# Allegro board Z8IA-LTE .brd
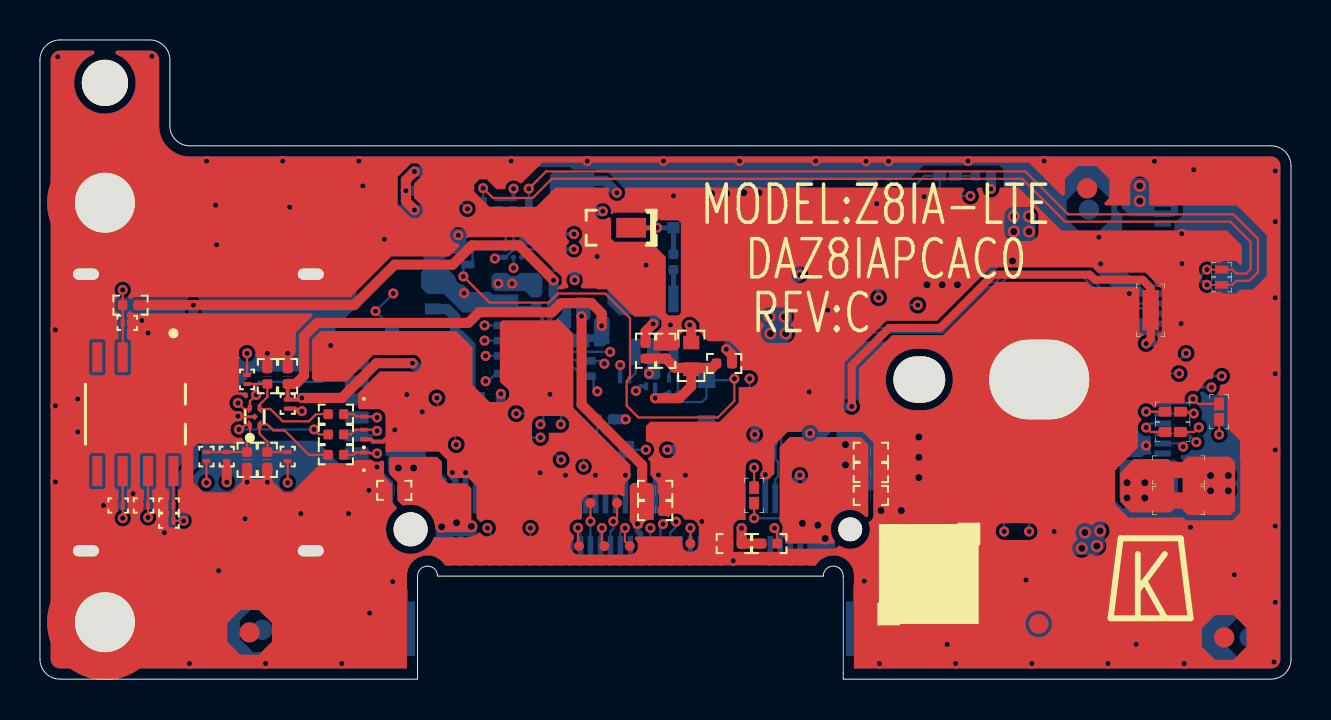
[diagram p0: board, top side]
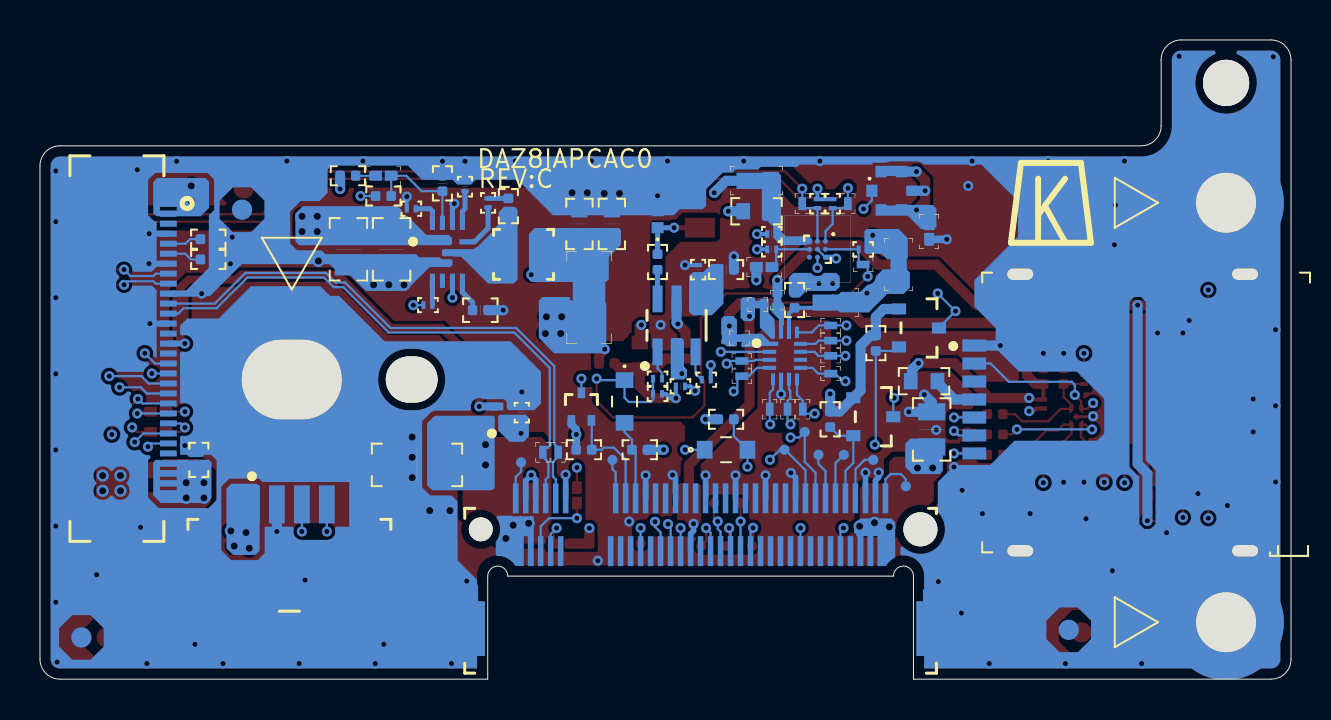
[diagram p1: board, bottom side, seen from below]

Outline 62.6 x 32 mm; copper layers: TOP, SGND, IN1, SVCC, IN2, IN3, SGND1, IN4, SGND2, BOTTOM. Coordinates in mm from the lower left corner of the outline.
Outline path: 0,31 0,1 arc(0.29,0.29) 1,0 18.89,0 18.89,5.16 arc(19.39,5.66) 19.89,5.16 39.19,5.16 arc(39.69,5.66) 40.19,5.16 40.19,0 61.6,0 arc(62.31,0.29) 62.6,1 62.6,25.7 arc(62.31,26.41) 61.6,26.7 7.5,26.7 arc(6.79,26.99) 6.5,27.7 6.5,31 arc(6.21,31.71) 5.5,32 1,32 arc(0.29,31.71) 0,31

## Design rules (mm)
constraint set DEFAULT: min track width 0.114
net group DFP-S4.5(3.5: nets USB2_3_A1_S_N USB2_3_A1_S_N_R USB2_3_A1_S_P USB2_3_A1_S_P_R
net group W4.5(3.5: nets 2ND_MBCLK 2ND_MBDATA I2C_DX_LTE_1V8_RSUB_SCL I2C_DX_LTE_1V8_RSUB_SDA

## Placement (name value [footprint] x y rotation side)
C1  *0.1u/50V_4  [C0402]  54.65 10.98 270 bottom
C2  USIM@0.1u/50V_4  [C0402]  12.39 15.17 270 top
C3  USIM@33p/50V_4  [C0402]  10.36 10.98 270 top
C4  USIM@33p/50V_4  [C0402]  11.38 10.98 270 top
C5  USIM@33p/50V_4  [C0402]  11.38 15.17 90 top
C6  1u/6.3V_4  [C0402]  34.72 6.79 0 top
C7  0.1u/50V_4  [C0402]  41.58 11.36 180 top
C8  100u/6.3V_12  [C1206]  43.73 10.72 180 bottom
C9  33p/50V_4  [C0402]  41.58 10.34 180 top
C10  10P/50V_4  [C0402]  41.58 9.2 180 top
C11  1u/10V_2  [C0201]  38.49 13.34 90 bottom
C14  0.1u/50V_4  [C0402]  30.78 9.45 180 top
C15  33p/50V_4  [C0402]  30.78 8.44 0 top
C16  22U/6.3V_8  [C0805]  17.98 12.5 270 bottom
C17  330p/25V_4  [C0402]  17.73 9.45 0 top
C18  ESIM@1u/6.3V_2  [C0201]  6.45 7.93 0 top
C19  ESIM@0.1u/16V_2  [C0201]  6.45 8.69 0 top
C21  ESIM@33p/25V_2  [C0201]  5.18 8.69 0 top
C22  ESIM@33p/25V_2  [C0201]  3.91 8.69 0 top
C23  ESIM@33p/25V_2  [C0201]  4.36 17.84 180 top
C24  22u/25V_8  [C0805]  45 21.52 90 bottom
C25  0.22u/25V_4  [C0402]  39.16 23.68 90 bottom
C26  *22u/25V_8  [C0805]  47.16 21.52 90 bottom
C27  1u/10V_2  [C0201]  41.33 24.66 90 bottom
C28  *P4@1u/6.3V_2  [C0201]  30.55 14.66 180 bottom
C29  *P4@100p/50V_4  [C0402]  31.32 16.44 270 top
C30  10u/16V_6  [C0603]  33.98 22.79 270 bottom
C31  10u/16V_6  [C0603]  35.61 22.79 270 bottom
C32  *1u/16V_4  [C0402]  42.46 24.82 270 bottom
C33  4.7u/10V_4  [C0402_2]  40.56 18.47 0 bottom
C34  *P4@1u/6.3V_2  [C0201]  29.67 20.5 90 bottom
C35  *P4@100p/50V_4  [C0402]  28.27 20.5 0 bottom
C45636  SPIN@0.1u/25V_2  [C0201]  25.98 22.28 0 bottom
C45637  SPIN@0.1u/25V_2  [C0201]  25.98 21.52 0 bottom
CN1  50278-00401-V01  [WTB-50278-00401-V01-4P-L]  50.12 3.83 180 bottom
CN3  APCI0157-P001A  [NGFF-APCI0157-P001A-75P-KB]  29.54 7.5 180 bottom
CN4  51540-03001-V01  [51540-03001-V01-30P-L]  59.35 16.55 270 bottom
CN5  USIM@155-1001302601  [SIMCARD-155-1001302601-7P-R]  7.25 13.35 90 bottom
D1  USIM@MESD11LH5.0CT5G  [R0201]  12.39 13.77 270 top
D2  USIM@TPD4E101DPWR  [SON4-0_8X0_8-48-5P-0_4H]  10.74 13.14 270 top
D3  *P4@AZ5325-01F.R7GR  [D-1X0_6-0_6H]  31.7 23.03 90 bottom
D26  RB500V-40  [D-1_85X1_25-2P-0_95H]  33.35 13.9 270 bottom
D13142  USIM@PESD5V0F1BSF  [D-0_6X0_3-0_32H-SMT]  16.2 11.11 90 top
D13143  USIM@PESD5V0F1BSF  [D-0_6X0_3-0_32H-SMT]  16.2 12.25 90 top
D13144  USIM@PESD5V0F1BSF  [D-0_6X0_3-0_32H-SMT]  16.2 13.39 270 top
D13145  RB500V-40  [D-1_85X1_25-2P-0_95H]  28.27 11.49 180 bottom
F1  USIM@SMD0603P100SLR/1A/6V_0603  [R0603]  18.36 14.92 0 bottom
HOLE1  *h-c228d118p2  [H-C228D118P2]  3.25 23.85 0 top
HOLE2  *h-c228d118p2  [H-C228D118P2]  3.25 2.85 0 top
HOLE3  *h-c315d197x157p2  [H-C315D197X157P2]  50 15 0 top
HOLE4  *h-o102x91d102x91n  [H-O102X91D102X91N]  44 15 0 top
HOLE5  *h-c91d91n  [H-C91D91N]  3.25 29.85 0 top
J11  SPIN@20449-001E  [ANTENNA-20449-001E-4P]  20 24.45 270 bottom
L1  2.2uH_3.2x2.5x1.5  [L3X2_5-1_5]  38.4 21.27 180 bottom
L2  USIM@BLM15PX330SN1D  [R0402]  14.81 13.26 180 top
L3  USIM@BLM15PX330SN1D  [R0402]  14.81 12.25 180 top
L4  USIM@BLM15PX330SN1D  [R0402]  14.81 11.23 180 top
NOREF  -  [unnamed]  44.47 5.26 0 top
NOREF#2  -  [#2]  23.8 -31.19 0 top
NOREF#3  -  [#2]  55.59 5.05 0 top
NOREF#4  -  [#2]  -27 -71.32 0 top
NOREF#5  -  [unnamed#3]  52.4 24.57 0 top
NOREF#6  -  [unnamed#3]  10.49 2.34 180 top
NOREF#7  -  [unnamed#3]  59.26 2.09 0 top
NOREF#8  -  [#2]  12 23.85 180 bottom
NOREF#9  -  [unnamed#3]  60.53 2.09 180 bottom
NOREF#10  -  [unnamed#3]  11.12 2.47 0 bottom
NOREF#11  -  [unnamed#3]  52.49 23.5 180 bottom
Q1  PMZ370UNE  [ESD3-0_985X0_585]  39.76 13.3 270 bottom
Q2  2N7002KTB  [SOT23-1_38-5-3P]  35.51 13.65 270 bottom
Q3  PJA138K  [SOT23-2-95-3P]  20.9 13.14 0 bottom
Q4  PJA138K  [SOT23-2-95-3P]  18.62 17.58 0 bottom
R1  *Short_4  [S0402]  56.68 12.38 0 top
R3  *Short_4  [S0402]  56.68 13.39 180 top
R4  USIM@15K_5%_2  [R0201]  9.35 11.14 90 top
R5  USIM@22_5%_2  [R0201]  10.36 15 270 top
R6  USIM@22_5%_2  [R0201]  12.39 11.14 90 top
R7  USIM@22_5%_2  [R0201]  8.33 11.14 90 top
R8  *Short_4  [S0402]  35.73 9.2 90 top
R9  10K_5%_4  [R0402]  36.5 6.79 180 top
R10  *EM06@Short_2  [S0201]  37.44 11.36 90 bottom
R11  *EM06@Short_2  [S0201]  36.67 11.36 90 bottom
R12  10K_5%_4  [R0402]  35.38 11.49 0 bottom
R13  10K_5%_4  [R0402]  32.59 11.49 0 bottom
R17  *EM06@Short_2  [S0201]  26.69 18.75 180 bottom
R32  10K_5%_4  [R0402]  23.06 13.01 90 bottom
R33  *P4@470_1%_4  [R0402]  31.7 20.88 90 bottom
R34  3.3_1%_2  [R0201]  40.18 23.84 90 bottom
R35  *Short_12  [S1206]  35.13 19.11 90 bottom
R36  *P4@43_5%_4  [R0402]  30.3 16.44 270 top
R37  *P4@4.7K_1%_2  [R0201]  31.7 14.28 0 bottom
R38  *P4@0_5%_2  [R0201]  29.26 14.99 180 bottom
R39  10K_1%_2  [R0201]  44.02 23.55 0 bottom
R40  100K_1%_2  [R0201]  43.19 18.73 0 bottom
R41  *Short_4  [S0402]  59 13.39 270 top
R42  10K_5%_4  [R0402]  20.78 16.82 90 bottom
R59  *EM06@Short_2  [S0201]  23.03 15.3 180 bottom
R60  *EM06@Short_2  [S0201]  26.08 13.52 270 bottom
R61  *EM06@Short_2  [S0201]  23.03 17.71 180 bottom
R62  *EM06@Short_2  [S0201]  27.61 17.07 0 bottom
R63  *EM06@Short_2  [S0201]  25.7 18.98 90 bottom
R64  *EM06@Short_2  [S0201]  27.48 15.93 0 bottom
R65  *EM06@Short_2  [S0201]  25.19 13.52 270 bottom
R66  *EM06@Short_2  [S0201]  23.03 16.19 180 bottom
R75  *EM06@Short_2  [S0201]  27.48 15.17 180 bottom
R76  *EM06@Short_2  [S0201]  24.43 13.52 90 bottom
R77  *EM06@Short_2  [S0201]  23.03 16.95 0 bottom
R299  SPIN@2.2K_1%_2  [R0201]  22.93 23.81 90 bottom
R316  SPIN@2.2K_1%_2  [R0201]  23.7 23.81 90 bottom
R343  *P4@0.01_1%_6  [R0603]  32.59 16.19 90 top
R344  **P4@0_5%_4  [R0402]  34.24 15.8 0 top
R345  *Short_0603  [S0603]  22.93 18.85 180 bottom
R346  *0_5%_4  [R0402]  24.84 18.98 90 bottom
R347  ESIM@10K_5%_4  [R0402]  4.53 18.73 180 top
R348  10K_5%_4  [R0402]  47.19 25.2 180 bottom
R349  *Short_4  [S0402]  45.41 25.2 180 bottom
R350  *0_5%_4  [R0402]  45.41 24.19 0 bottom
R558_46  SPIN@2.2K_1%_2  [R0201]  21.41 21.52 180 bottom
R4700  *SPIN@Short_0201  [S0201]  24.46 23.81 90 bottom
R4701  *SPIN@Short_0201  [S0201]  22.17 23.81 90 bottom
R4702  *SPIN@Short_0201  [S0201]  21.41 20.76 180 bottom
R4704  *SPIN@Short_0402  [S0402]  26.36 20.63 180 bottom
R4705  *SPIN@Short_0402  [S0402]  18.11 22.41 270 bottom
R69070  ESIM@0_5%_4  [R0402]  54.18 22.03 180 bottom
R69071  USIM@0_5%_4  [R0402]  54.18 21.01 180 bottom
R69072  *Short_0603  [S0603]  56.97 10.47 180 top
R69073  *Short_0603  [S0603]  56.97 8.95 180 top
R69074  *Short_0603  [S0603]  55.57 18.47 270 top
R69075  *P4@0_5%_2  [R0201]  31.7 15.04 0 bottom
R69076  *SPIN@Short_0603  [S0603]  26.74 24.95 180 bottom
R69077  *SPIN@Short_0603  [S0603]  19.63 20.76 270 bottom
R69078  *SPIN@0.01_1%_6  [R0603]  26.74 23.42 180 bottom
R69079  10K_5%_4  [R0402]  28.27 13.01 0 bottom
R69080  *Short_0201  [S0201]  59.13 19.74 0 top
R69081  *Short_0201  [S0201]  59.13 20.5 0 top
SPR1  *P4@FDZDJ00101  [EMIPAD59X39]  28.43 22.6 180 top
TP1  *TP  [TP2050]  32.54 6.79 0 top
TP2  *TP  [TP2050]  33.96 10.98 180 bottom
TP3  *TP  [TP2050]  20.9 10.98 180 bottom
TP4  *TP  [TP2050]  19.27 9.66 180 bottom
TP5  *TP  [TP2050]  38.53 10.85 180 bottom
TP6  *TP  [TP2050]  25.35 11.49 180 bottom
TP7  *TP  [TP2050]  24.33 12.38 180 bottom
TP8  *TP  [TP2050]  23.65 11.23 180 bottom
TP9  *TP  [TP2050]  22.38 11.23 180 bottom
TP10  *TP  [TP2050]  29.51 6.66 0 top
TP11  *TP  [TP2050]  26.97 6.66 0 top
TP12  *TP  [TP2050]  28.24 6.66 0 top
TP13  *TP  [TP2050]  28.88 8.82 0 top
TP14  *TP  [TP2050]  27.54 8.82 0 top
U1  NX3DV2567GU  [QFN16-2_6X1_8-4-0_55H]  25.32 16.19 270 bottom
U4  NB680GD-Z  [QFN12-2X3-5]  42.21 21.39 270 bottom
U5  *P4@IQS231A01311000TSR  [TSOT23-6-2_8-95-6P-1_1H]  30.75 17.71 270 bottom
U6  ESIM@MFF2-EUICC-MFONLY  [DFN8-6X5-1_27-9P-0_95H]  4.77 13.26 180 top
U9314  SPIN@SX9310ICSTRT  [BGA9-SEMTECH-SX9310]  23.7 21.52 0 bottom

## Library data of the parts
C1 C2 C6-C11 C14 C19 C21 C24-C35 C45636 C45637 = CAP_NON-POL_BGM
C3-C5 C15 = CAP_NP
C16 = C_7
C17 C18 C22 C23 = CAP NON-POL_BGM
CN1 = 50278-00401-V01_4P_BGM
CN3 = NGFF_79P_BKEY_BGM
CN4 = FFCFPC_30P_BGM
CN5 = SIMCARD_7P_4F_BGM
D1 = ZENER-2_0
D2 = TPD4E101DPWR_2
D3 D13142-D13144 = TVS_DIODE_BGM
D26 D13145 = Schottky_DIODE_BGM
F1 = FUSE_BGM
HOLE1-HOLE5 = 3x2_6.1
J11 = RF_4P_V2_BGM
L1 = INDUCTOR_BGM
L2-L4 = BEAD_BGM
Q1 = MOS-N_3P_ESD_123_1_BGM
Q2-Q4 = MOS-N_3P_ESD_BGM
R1 R3-R13 R17 R32-R42 R59-R66 R75-R77 R299 R316 R344 R346-R350 R558_46 R69070 R69071 R69075 R69079 = RES_BGM
R343 R69078 = R_Current_SEN_BGM
R345 R4700-R4702 R4704 R4705 R69072-R69074 R69076 R69077 R69080 R69081 = SHORTPAD_V01_BGM
SPR1 = SPRING_BGM
TP1-TP14 = TP_BGM
U1 = NX3DV2567GU_16P_BGM
U4 = NB680
U5 = IQS231A_6P_BGM
U6 = MFF2-EUICC-MFONLY_8P_BGM
U9314 = SX9310ICSTRT_9P_BGM

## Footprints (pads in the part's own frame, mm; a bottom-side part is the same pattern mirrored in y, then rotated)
51540-03001-V01-30P-L
  rect 0.305x0.838 smd: 1(-7.25,3.175) 2(-6.75,3.175) 3(-6.25,3.175) 4(-5.75,3.175) 5(-5.25,3.175) 6(-4.75,3.175) 7(-4.25,3.175) 8(-3.75,3.175) 9(-3.25,3.175) 10(-2.75,3.175) 11(-2.25,3.175) 12(-1.75,3.175) 13(-1.25,3.175) 14(-0.75,3.175) 15(-0.25,3.175) 16(0.25,3.175) 17(0.75,3.175) 18(1.25,3.175) 19(1.75,3.175) 20(2.25,3.175) 21(2.75,3.175) 22(3.25,3.175) 23(3.75,3.175) 24(4.25,3.175) 25(4.75,3.175) 26(5.25,3.175) 27(5.75,3.175) 28(6.25,3.175) 29(6.75,3.175) 30(7.25,3.175)
  rect 0.787x2.007 smd: 31(-8.95,0) 32(8.95,0)
ANTENNA-20449-001E-4P
  rect 0.61x0.559 smd: 1(0,-0.975)
  custom 0.145x0.145 smd: 2(0.96,0) 3(-0.96,0)
  rect 0.508x0.508 smd: 4(0,1)
BGA9-SEMTECH-SX9310
  round 0.254 smd: A1(-0.4,-0.4) A2(-0.4,0) A3(-0.4,0.4) B1(0,-0.4) B2(0,0) B3(0,0.4) C1(0.4,-0.4) C2(0.4,0) C3(0.4,0.4)
C0201
  rect 0.203x0.381 smd: 1(-0.225,0) 2(0.225,0)
C0402
  custom 0.12x0.12 smd: 1(0.39,0) 2(-0.39,0)
C0402_2
  custom 0.12x0.12 smd: 1(0.39,0) 2(-0.39,0)
C0603
  rect 0.686x0.813 smd: 1(0.6,0) 2(-0.6,0)
C0805
  rect 0.864x1.372 smd: 1(0.88,0) 2(-0.88,0)
C1206
  rect 1.219x1.626 smd: 1(1.4,0) 2(-1.4,0)
D-0_6X0_3-0_32H-SMT
  custom 0.051x0.051 smd: 1(-0.242,0) 2(0.242,0)
D-1_85X1_25-2P-0_95H
  rect 0.787x0.889 smd: 1(-1.07,0) 2(1.07,0)
D-1X0_6-0_6H
  rect 0.559x0.61 smd: 1(-0.425,0) 2(0.425,0)
DFN8-6X5-1_27-9P-0_95H
  rect 0.508x1.499 smd: 1(-1.905,-2.85) 2(-0.635,-2.85) 3(0.635,-2.85) 4(1.905,-2.85) 5(1.905,2.85) 6(0.635,2.85) 7(-0.635,2.85) 8(-1.905,2.85)
  rect 4.191x3.404 smd: 9(0,0)
EMIPAD59X39
  rect 1.499x0.991 smd: 1(-1.15,0)
ESD3-0_985X0_585
  custom 0.062x0.062 smd: 1(0.35,-0.225) 2(0.35,0.225)
  custom 0.1x0.1 smd: 3(-0.35,0)
H-C91D91N
  round 2.311 hole 2.311 unplated: (0,0)
H-C228D118P2
  round 5.791 hole 2.997: 1(0,0)
H-C315D197X157P2
  round 8.001 hole 5.004x3.988: 1(0,0)
H-O102X91D102X91N
  oval 2.591x2.311 hole 2.591x2.311 unplated: (0,0)
L3X2_5-1_5
  rect 1.245x1.194 smd: 1(-1.125,0) 2(1.125,0)
NGFF-APCI0157-P001A-75P-KB
  round 1.194 hole 1.194 unplated: (-11,0)
  round 1.702 hole 1.702 unplated: (11,0)
  rect 0.279x1.499 smd: 1(-9.25,1.55) 2(-9,-1.09) 3(-8.75,1.55) 4(-8.5,-1.09) 5(-8.25,1.55) 6(-8,-1.09) 7(-7.75,1.55) 8(-7.5,-1.09) 9(-7.25,1.55) 10(-7,-1.09) 11(-6.75,1.55) 20(-4.5,-1.09) 21(-4.25,1.55) 22(-4,-1.09) 23(-3.75,1.55) 24(-3.5,-1.09) 25(-3.25,1.55) 26(-3,-1.09) 27(-2.75,1.55) 28(-2.5,-1.09) 29(-2.25,1.55) 30(-2,-1.09) 31(-1.75,1.55) 32(-1.5,-1.09) 33(-1.25,1.55) 34(-1,-1.09) 35(-0.75,1.55) 36(-0.5,-1.09) 37(-0.25,1.55) 38(0,-1.09) 39(0.25,1.55) 40(0.5,-1.09) 41(0.75,1.55) 42(1,-1.09) 43(1.25,1.55) 44(1.5,-1.09) 45(1.75,1.55) 46(2,-1.09) 47(2.25,1.55) 48(2.5,-1.09) 49(2.75,1.55) 50(3,-1.09) 51(3.25,1.55) 52(3.5,-1.09) 53(3.75,1.55) 54(4,-1.09) 55(4.25,1.55) 56(4.5,-1.09) 57(4.75,1.55) 58(5,-1.09) 59(5.25,1.55) 60(5.5,-1.09) 61(5.75,1.55) 62(6,-1.09) 63(6.25,1.55) 64(6.5,-1.09) 65(6.75,1.55) 66(7,-1.09) 67(7.25,1.55) 68(7.5,-1.09) 69(7.75,1.55) 70(8,-1.09) 71(8.25,1.55) 72(8.5,-1.09) 73(8.75,1.55) 74(9,-1.09) 75(9.25,1.55)
  rect 1.194x2.743 smd: 76(-11.385,-4.97) 77(11.385,-4.97)
QFN12-2X3-5
  rect 0.254x1.499 smd: 1(-0.5,-0.55) 2(0.5,-0.55) 7(0,0.55)
  rect 0.711x0.254 smd: 3(1.45,-0.75) 4(1.45,-0.25) 5(1.45,0.25) 6(1.45,0.75) 9(-1.45,0.75) 10(-1.45,0.25) 11(-1.45,-0.25) 12(-1.45,-0.75)
  rect 0.254x0.711 smd: 8(-0.5,0.95)
QFN16-2_6X1_8-4-0_55H
  rect 0.203x0.762 smd: 1(-0.6,-0.725)
  rect 0.203x0.66 smd: 2(-0.2,-0.775) 3(0.2,-0.775) 4(0.6,-0.775) 9(0.6,0.775) 10(0.2,0.775) 11(-0.2,0.775) 12(-0.6,0.775)
  rect 0.584x0.203 smd: 5(1.175,-0.6) 8(1.175,0.6) 13(-1.175,0.6) 15(-1.175,-0.2) 16(-1.175,-0.6)
  rect 0.66x0.203 smd: 6(1.175,-0.2) 7(1.175,0.2) 14(-1.175,0.2)
R0201
  rect 0.203x0.381 smd: 1(-0.225,0) 2(0.225,0)
R0402
  custom 0.12x0.12 smd: 1(0.39,0) 2(-0.39,0)
R0603
  rect 0.686x0.813 smd: 1(0.6,0) 2(-0.6,0)
S0201
  rect 0.343x0.381 smd: 1(-0.225,0) 2(0.225,0)
S0402
  custom 0.125x0.125 smd: 1(0.39,0) 2(-0.39,0)
S0603
  rect 1.041x0.813 smd: 1(0.6,0) 2(-0.6,0)
S1206
  rect 2.032x1.626 smd: 1(1.4,0) 2(-1.4,0)
SIMCARD-155-1001302601-7P-R
  rect 0.61x1.194 smd: 1(3.35,8.6) 2(2.45,8.6) 3(1.55,8.6) 4(0.65,8.6) 5(-0.25,8.6) 6(-1.15,8.6) 7(-2.05,8.6)
  oval 1.143x1.905 hole 0.559x1.295: 8(-6.925,6.3) 9(-6.925,-4.95) 10(6.925,-4.95) 11(6.925,6.3)
SON4-0_8X0_8-48-5P-0_4H
  custom 0.055x0.055 smd: 1(0.39,-0.24) 2(0.39,0.24) 3(-0.39,0.24) 4(-0.39,-0.24)
  custom 0.088x0.088 smd: 5(0,0)
SOT23-1_38-5-3P
  rect 0.533x0.381 smd: 1(0.69,0.5) 2(0.69,-0.5) 3(-0.69,0)
SOT23-2-95-3P
  rect 0.711x0.559 smd: 1(1,0.95) 2(1,-0.95) 3(-1,0)
TP2050
  round 0.508 smd: 1(0,0)
TSOT23-6-2_8-95-6P-1_1H
  rect 1.346x0.508 smd: 1(1.325,-0.95) 2(1.325,0) 3(1.325,0.95) 4(-1.325,0.95) 5(-1.325,0) 6(-1.325,-0.95)
unnamed
  round 0.991 smd: (5.5,-2.5)
unnamed#3
  round 1.016 smd: 1(0,0)
WTB-50278-00401-V01-4P-L
  rect 0.787x1.905 smd: 1(-1.875,4.925) 2(-0.625,4.925) 3(0.625,4.925) 4(1.875,4.925)
  rect 1.295x3.353 smd: 5(-4.725,0) 6(4.725,0)

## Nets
3V_A_R: C30.1 C31.1 L1.2 R35.1 U4.5(VOUT)
3V_BST: R34.1 U4.8
3V_BSTR: C25.1 R34.2
3V_SW: C25.2 L1.1 U4.7
+1.8V_DX_LTE: C11.1 Q1.2(S) Q3.2 Q4.2 R13.2 R32.1 R42.1 R69078.2 R69079.1
+1.8V_S5: Q1.3 R69074.2 R69076.2
+3V: CN4.1 CN4.2 R343.1 R345.1 R348.2 R69077.1
+3V_DX_LTE: C6.1 C7.1 C8.1 C9.1 C10.1 C16.1 C17.1 CN1.1 CN3.2 CN3.4 CN3.70 CN3.72 CN3.74 Q1.1 Q2.2 R9.1 R12.1 R35.2 R40.2 R344.1 R346.1
+3V_SAR: C28.1 C29.1 R36.1 R37.1 R343.2 R344.2
+5VPCU: C24.1 C26.1 R69072.2 R69073.2 U4.1
GND: C1.2 C2.2 C3.1 C4.1 C5.1 C6.2 C7.2 C8.2 C9.2 C10.2 C11.2 C14.2 C15.1 C16.2 C17.2 C18.1 C19.1 C21.1 C22.1 C23.1 C24.2 C26.2 C27.2 C28.2 C29.2 C30.2 C31.2 C32.2 C33.2 C34.2 C35.2 CN1.2 CN1.5 CN1.6 CN3.3 CN3.5 CN3.11 CN3.27 CN3.33 CN3.39 CN3.45 CN3.51 CN3.57 CN3.71 CN3.73 CN3.76 CN3.77 CN4.4 CN4.7 CN4.10 CN4.13 CN4.31 CN4.32 CN5.1 CN5.8 CN5.9 CN5.10 CN5.11(GND_4) D1.2 D2.5(GND) D3.2 D13142.1 D13143.1 D13144.1 HOLE1.1 HOLE2.1 HOLE3.1 R38.2 R39.2 R4705.1 R69070.1 R69071.1 U1.6 U4.2 U4.10 U5.2(VSS) U6.1 U6.2 U6.9
2ND_MBCLK: D13145.1(CATHODE) R4700.2 R69080.2
2ND_MBDATA: R4701.2 R69081.2
+ESIM_PWR: C18.2 C19.2 R63.2 R347.2 U6.8(VCC)
+ESIM_PWR_S: R63.1 U1.15
+LTE_SIM_PWR: C14.1 C15.2 CN3.36 R17.1
+SIM_PWR: C2.1 D1.1 F1.1 R4.1 R62.2
+SIM_PWR_S: R62.1 U1.1
+USIM_PWR: R17.2 U1.16
ANTCTL0: CN1.3 CN3.59 TP6.1
ANTCTL1: CN1.4 CN3.61 TP7.1
ANTCTL2: CN3.63 TP8.1
ANTCTL3: CN3.65 TP9.1
BOARD_ID8_SIM_TYPE1: CN4.6 R69071.2
BOARD_ID9_SIM_TYPE2: CN4.5 R69070.2
BODY_SAR_ODL: CN3.25 D26.2 R13.1
CONFIG_0: CN3.21 TP2.1
CONFIG_1: CN3.69 TP3.1
CONFIG_2: CN3.75 TP4.1
CONFIG_3: CN3.1 TP5.1
CONN_LTE_WAKE_L: CN3.23 Q2.1(S) R12.2
CX: R33.2 U5.6
DDR4_SUSON_2V5: CN4.25 R350.1
EC_LTE_GPS_OFF_ODL: CN3.26 TP1.1
EC_SIM_DET: CN4.19 Q4.3
EC_SIM_DET_LTE: CN3.66 Q4.1(S) R42.2
EC_SIM_SW#: CN4.18 U1.2
EN_3V_DX_LTE: CN4.24 R8.1
EN_3V_DX_LTE_R: CN3.6 R8.2
ENCLK: R39.1 U4.12
ESIM_CLK: C22.2 R64.2 U6.6
ESIM_CLK_S: R64.1 U1.3
ESIM_DATA: C23.2 R65.2 R347.1 U6.3
ESIM_DATA_S: R65.1 U1.7
ESIM_RST#: C21.2 R66.2 U6.7
ESIM_RST#_S: R66.1 U1.11
I2C_DX_LTE_1V8_RSUB_SCL: R316.1 R4700.1 U9314.B1
I2C_DX_LTE_1V8_RSUB_SDA: R299.1 R4701.1 U9314.A1
IO2: R38.1 U5.3
LTE_BODY_SAR_ODL: CN4.17 D26.1(CATHODE) R37.2 R4702.2 R69075.2
LTE_OFF_ODL: CN3.8(W_DISABLE#1_3.3V) R9.2 R41.1
LTE_OFF_ODL_R: CN4.21 R41.2
LTE_OFF_ODL_RST: CN4.23 R1.2
LTE_SIM_CLK: CN3.32 R75.1
LTE_SIM_DATA: CN3.34 R76.1
LTE_SIM_RST#: CN3.30 R77.1
NB680_VCC_BYP: C27.1 U4.9
P_SENS_CS1: J11.1 U9314.B3
P_SENSOR_INT_RSUB_L: R558_46.1 R4702.1 U9314.A2
PCIE_WAKE#: Q2.3 R3.1
PCIE_WAKE#_R: CN4.22 R3.2
PLT_RST_LTE_L: CN3.67 Q3.1(S) R32.2
PLTRST#: Q3.3 R1.1
PP3300_A: R299.2 R316.2 R558_46.2 R4704.2 R69077.2
SIM_CLK: R6.1 R60.2
SIM_CLK_S: R60.1 U1.5
SIM_DATA: R7.1 R59.2
SIM_DATA_S: R59.1 U1.9
SIM_RST#: R5.1 R61.2
SIM_RST#_S: R61.1 U1.13
SX9310_GND: C45636.2 C45637.2 J11.2 J11.3 J11.4(GND_3) R4705.2 U9314.A3 U9314.B2
USB2_3_A1_S_N: CN4.11 R11.2
USB2_3_A1_S_N_R: CN3.9 R11.1
USB2_3_A1_S_P: CN4.12 R10.2
USB2_3_A1_S_P_R: CN3.7 R10.1
USIM2_CLK: CN3.44 TP12.1
USIM2_DATA: CN3.42 TP13.1
USIM2_DET: CN3.40 TP10.1
USIM2_RESET: CN3.46 TP14.1
USIM2_VDD: CN3.48 TP11.1
USIM_CLK: R75.2 U1.4
USIM_CLK_R: C4.2 D2.2 L4.1 R6.2
USIM_CLK_R_L: CN5.7 D13142.2 L4.2
USIM_DATA: R76.2 U1.8
USIM_DATA_R: C3.2 D2.1 L3.1 R4.2 R7.2
USIM_DATA_R_L: CN5.6 D13143.2 L3.2
USIM_DET#: CN4.20 CN5.2 D2.4
USIM_RST#: R77.2 U1.12
USIM_RST_L: C5.2 D2.3 L2.1 R5.2
USIM_RST_L_L: CN5.5 D13144.2 L2.2
N157273: C32.1 R349.1 R350.2 U4.11
N157401: C33.1 U4.6
N157503: R40.1 U4.3
N170613: C34.1 C35.1 U5.4
N170649: R36.2 U5.5
N170657: D3.1 R33.1 SPR1.1
N194065: C1.1 CN4.27 CN4.28 CN4.29 CN4.30 R69072.1 R69073.1
N213722: CN4.15 R69074.1
N15816409: R345.2 R346.2 U1.14(VCC)
N15891397: R348.1 R349.2
N15913509: CN5.4 F1.2
N15931362: R69075.1 U5.1
N15932419: C45636.1 R69076.1 R69078.1 U9314.C1
N15932503: C45637.1 R4704.1 U9314.C2(VDD)
N15934474: CN3.58 D13145.2 R69079.2
N15935166: CN4.9 R69080.1
N15935178: CN4.8 R69081.1

Pads without a net: CN3 10 20 22 24 28 29 31 35 37 38 41 43 47 49 50 52 53 54 55 56 60 62 64 68; CN4 3 14 16 26; CN5 3; NOREF#5 1; NOREF#6 1; NOREF#7 1; NOREF#9 1; NOREF#10 1; NOREF#11 1; U1 10; U4 4; U6 4 5; U9314 C3

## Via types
v1: diameter 0.508, hole 0.254, TOP to BOTTOM, 213 vias
v2: diameter 0.61, hole 0.356, TOP to BOTTOM, 45 vias

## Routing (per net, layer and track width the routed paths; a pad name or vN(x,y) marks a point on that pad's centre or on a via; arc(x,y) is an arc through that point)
3V_A_R: length 5.3
  IN1 w0.305: v1(41.96,19.1) 39.17,19.1 v1(38.02,20.25)
  BOTTOM w0.254: U4.5 v1(41.96,19.1)
3V_BST: length 2.4
  BOTTOM w0.254: U4.8 40.86,21.89 40.18,22.57 R34.1
3V_BSTR: length 1
  BOTTOM w0.254: C25.1 R34.2
+1.8V_DX_LTE: length 46.3
  IN1 w0.508: v1(23.06,14.28) 23.95,15.17 25.6,15.17 27.76,13.01 v1(29.31,13.01) 29.87,13.01 v1(31.39,11.49) 37.71,11.49 v1(38.53,12.31)
  IN4 w0.508: v1(38.53,12.31) 38.53,13.19 32.71,19 32.71,22.92 32.21,23.42 31.29,23.42 31.02,23.69 28.43,23.69 v1(28.16,23.42)
  BOTTOM w0.508: Q4.2 20.38,18.53 20.78,18.14 R42.1 21.03,17.21 21.54,16.7 21.54,14.45 Q3.2 22.59,13.4 R32.1 v1(23.06,14.28) ; R69079.1 v1(29.31,13.01) ; R13.2 v1(31.39,11.49) ; R69078.2 v1(28.16,23.42)
+1.8V_S5: length 41.4
  TOP w0.406: v1(40.62,13.65) 40.62,15.71 42.49,17.58 45.03,17.58 47.7,20.25 52.53,20.25 52.78,20 55.17,20 55.57,19.59 R69074.2
  IN4 w0.508: v1(28.87,24.35) 30.78,24.35 31.24,24.81 32.33,24.81 32.95,24.19 32.95,23.64 33.32,23.27 33.32,19.54 37.38,15.48 38.79,15.48 v1(40.62,13.65)
  BOTTOM w0.406: Q1.3 v1(40.62,13.65)
  BOTTOM w0.508: R69076.2 28.27,24.95 v1(28.87,24.35)
+3V: length 3
  TOP w0.508: v1(32.51,17.73) 32.59,17.66 R343.1
  BOTTOM w0.508: R348.2 v1(47.58,24.54) ; R345.1 21.69,18.85 v1(21.22,19.32)
  vias: v2(55.03,24.69) v2(55.03,23.93)
+3V_DX_LTE: length 4.7
  TOP w0.508: R9.1 C6.1 v1(35.11,7.56) ; v1(34.34,16.52) 34.63,16.23 R344.1
  BOTTOM w0.114: R40.2 v1(43.92,18.73)
  BOTTOM w0.381: R12.1 35.77,11.88 35.76,11.89 v1(35.76,12.25) 35.76,12.5 36.01,12.75 Q2.2
  vias: v1(22.93,19.8) v1(23.62,19.8) v2(17.93,10.57) v2(18.69,10.57) v2(20.1,7.63) v2(20.84,7.83) v2(21.59,7.65) v2(36.5,18.14) v2(36.55,17.3) v2(37.26,18.14) v2(37.31,17.3) v2(38.15,7.8) v2(38.92,7.71) v2(39.29,7.04) v2(40.31,11.74) v2(40.31,10.72) v2(52.13,6.55) v2(52.29,7.34) v2(52.88,6.66) v2(53.05,7.42)
+3V_SAR: length 8.2
  TOP w0.508: R344.2 33.63,15.59 R343.2 ; R343.2 31.78,15.59 C29.1 R36.1 ; R343.2 32.59,14.66 31.99,14.06 v1(30.78,14.06)
  BOTTOM w0.203: R37.1 31.28,14.28 31.06,14.06 v1(30.78,14.06) C28.1
+5VPCU:
  vias: v2(48.73,23.17) v2(48.73,22.41) v2(49.49,23.17) v2(49.49,22.41) v2(58.57,10.19) v2(58.57,9.43) v2(59.46,10.19) v2(59.46,9.43)
GND: length 79.1
  TOP w0.152: 9.93,13.14 D2.5
  TOP w0.178: v1(9.9,13.16) 9.93,13.14
  TOP w0.203: v1(6.23,7.33) C18.1 C19.1 ; D13144.1 17.74,13.63 v1(18.35,14.24) ; C22.1 v1(3.18,8.69) ; v1(5.1,17.96) 4.98,17.84 C23.1 ; D13143.1 16.55,12.01 16.66,11.89 17.17,11.89 v1(17.75,12.48) ; v1(13.11,13.42) 12.9,13.42 12.77,13.55 D1.2 ; v1(4.66,9.29) 4.96,8.99 C21.1
  TOP w0.508: C14.2 31.17,10 v1(30.95,10.22) ; C3.1 v1(10.36,9.86) ; C5.1 v1(11.38,16.31) ; v1(1.89,14.03) 4.01,14.03 U6.9 3.88,12.38 v1(1.89,12.38) ; C15.1 31.27,8.54 ; v2(42.08,8.44) 41.97,8.56 C10.2 ; C9.2 43.1,9.21 v2(43.1,8.44) ; C17.2 v1(16.46,9.45) ; C4.1 v1(11.38,9.86) ; v1(34.69,5.93) 34.33,6.29 C6.2 ; C2.2 v1(12.39,16.31) ; v1(31.55,17.73) 31.32,17.51 C29.2 ; 31.27,8.55 32.6,8.55 33.12,8.03 v1(33.12,7.89) ; U6.1 v1(6.68,17.33) ; U6.2 v1(5.41,17.33)
  BOTTOM w0.203: U1.6 v1(25.52,14.26) ; C34.2 v1(30.33,20.73) ; R38.2 v1(29.03,15.72) ; R39.2 v1(44.24,24.16) ; C28.2 30.05,14.66 v1(29.82,14.43)
  BOTTOM w0.254: v1(41.87,23.81) 41.96,23.71 U4.10
  BOTTOM w0.279: CN3.33 30.79,10.07 v1(30.95,10.22) ; CN3.45 v1(27.79,10.21) ; CN3.5 37.79,9.99 v1(38.02,10.22) 38.29,9.94 CN3.3 ; CN3.27 v1(32.29,10.21) ; CN3.71 v1(21.29,10.34) ; CN3.51 v1(26.29,10.21) ; v1(25.03,10.33) 24.79,10.1 CN3.57 ; v1(20.63,10.34) 20.63,10.1 20.79,9.94 CN3.73 ; CN3.11 v1(36.29,10.24) ; CN3.39 v1(29.29,10.21)
  BOTTOM w0.305: CN4.10 v1(54.51,19.3) ; CN4.4 v1(57.13,22.3) ; CN4.7 v1(57.14,20.8) ; v1(57.1,17.8) CN4.13
  BOTTOM w0.381: R4705.1 v1(17.23,22.02)
  BOTTOM w0.508: v1(18.35,14.24) 17.98,13.87 C16.2 v1(19.12,13.38) ; D3.2 v1(31.7,24.2) ; CN1.2 v1(50.75,7.39) ; v2(33.6,24.31) 33.6,23.77 C30.2 34.36,23.77 v2(34.36,24.31) ; C32.2 v1(42.46,25.93) ; CN3.76 40.93,4.59 v1(41.25,4.91) ; CN3.77 18.16,4.37 v1(17.65,4.88) ; CN4.31 v1(57.73,25.5) ; C33.2 v1(39.42,18.47) ; v1(55.35,11.7) 55.02,11.37 C1.2 ; v2(35.21,24.35) 35.21,23.78 C31.2 35.98,23.76 v2(35.98,24.35) ; C35.2 v1(27.88,21.16) ; CN1.6 v1(45.4,1.74) ; CN4.32 v1(57.57,7.6) ; CN5.1 v1(14.55,16.7) ; CN1.5 v1(54.84,1.74)
  vias: v1(0.77,17.49) v1(0.77,13.68) v1(0.77,9.87) v1(0.89,31.16) v1(5.6,31.18) v1(7.48,0.78) v1(8.34,25.94) v1(8.79,23.73) v1(8.84,21.75) v1(8.94,5.43) v1(10.26,8.03) v1(11.29,0.78) v1(12.15,25.94) v1(12.5,23.63) v1(13.05,8.29) v1(15.1,0.78) v1(15.44,8.29) v1(15.96,25.94) v1(16.15,24.69) v1(16.5,3.31) v1(16.87,10.62) v1(23.58,25.94) v1(27.39,25.94) v1(30.48,15.3) v1(31.2,25.94) v1(35.01,25.94) v1(38.49,14.38) v1(38.82,25.94) v1(41.33,25.93) v1(42.01,0.78) v1(45.82,0.78) v1(46.44,25.94) v1(49.34,4.96) v1(49.63,0.78) v1(50.25,25.94) v1(52.98,22.13) v1(53.07,20.8) v1(53.44,0.78) v1(55.76,25.93) v1(57.25,0.78) v1(59.76,5.23) v1(61.75,0.86) v1(61.81,25.44) v1(61.81,22.9) v1(61.81,19.09) v1(61.81,15.28) v1(61.81,11.47) v1(61.81,7.66) v1(61.81,3.85) v2(43.98,12.12) v2(43.98,11.11) v2(43.98,10.09) v2(44.38,19.74) v2(45.14,19.74) v2(45.91,19.74) v2(48.67,20.93)
2ND_MBCLK: length 59.5
  TOP w0.114: R69080.2 59.67,19.74 59.86,19.94 60.51,19.94 60.95,20.38 60.95,22.04 59.71,23.27 51.45,23.27 49.3,25.42 25.32,25.42 v1(24.46,24.55)
  IN4 w0.089: v1(24.46,24.55) 25.64,24.55 30.08,20.12 30.08,15.13 30.32,14.89 v1(30.32,11.49)
  BOTTOM w0.114: D13145.1 v1(30.32,11.49) ; R4700.2 v1(24.46,24.55)
2ND_MBDATA: length 43.6
  TOP w0.114: R69081.2 59.67,20.5 59.86,20.31 60.36,20.31 60.58,20.53 60.58,21.89 59.56,22.9 51.29,22.9 49.15,25.05 25.61,25.05 24.65,24.09 22.66,24.09 v1(22.17,24.58)
  BOTTOM w0.114: R4701.2 v1(22.17,24.58)
+ESIM_PWR: length 36.7
  TOP w0.114: v1(7.19,7.93) C18.2 C19.2 U6.8
  TOP w0.508: R347.2 v1(7.68,18.73) 15.72,18.73 17.75,20.75 20.65,20.75 21.61,21.72 23.95,21.72 v1(25.7,19.97)
  BOTTOM w0.508: v1(7.68,18.73) 7.68,10.78 7.19,10.29 v1(7.19,7.93)
+LTE_SIM_PWR: length 11.5
  TOP w0.508: C14.1 30.13,9.71 30.13,10.71 27.1,13.75 v1(27.1,18.17)
  BOTTOM w0.279: CN3.36 30.04,7.27 29.9,7.42 v1(29.9,7.78)
+SIM_PWR: length 36
  TOP w0.203: v1(13.11,14.08) 13.03,14 D1.1 C2.1
  TOP w0.254: R4.1 9.35,10.59
  TOP w0.508: v1(18.64,15.82) 16.84,15.82 15.1,14.08 v1(13.11,14.08) ; C2.1 12.79,14.78 13.21,15.19 13.21,17.18 13.87,17.84 21.44,17.84 21.97,18.37 25.63,18.37 26.08,18.83 27.6,18.83 28.1,18.32 v1(28.1,17.68) ; 9.35,10.59 v1(9.35,9.86)
  IN2 w0.508: v1(9.35,9.86) 10.57,11.08 11.89,11.08 12.39,11.59 12.39,13.67 12.8,14.08 v1(13.11,14.08)
  BOTTOM w0.508: v1(18.64,15.82) 18.96,15.5 F1.1
ANTCTL0: length 34.8
  IN1 w0.089: v1(49.49,7.39) 47.81,9.08 38.34,9.08 37.41,8.15 37.41,7.4 36.98,6.97 26.11,6.97 25.8,7.28 25.8,10.71 v1(26.08,10.98)
  BOTTOM w0.114: CN3.59 24.29,10.46 25.32,11.49 TP6.1 25.57,11.49 v1(26.08,10.98) ; CN1.3 v1(49.49,7.39)
ANTCTL1: length 35.7
  IN1 w0.089: v1(48.25,7.39) 46.75,8.89 38.42,8.89 37.6,8.07 37.6,7.32 37.06,6.78 26.03,6.78 25.61,7.2 25.61,11.71 25.22,12.1 v1(25.04,12.1)
  BOTTOM w0.114: v1(25.04,12.1) 24.61,12.1 TP7.1 24.33,10.88 23.79,10.34 CN3.61 ; CN1.4 v1(48.25,7.39)
ANTCTL2: length 2.3
  BOTTOM w0.114: CN3.63 23.29,10.42 23.65,10.77 TP8.1
ANTCTL3: length 2.4
  BOTTOM w0.114: TP9.1 22.79,10.81 CN3.65
BOARD_ID8_SIM_TYPE1: length 1.7
  BOTTOM w0.114: R69071.2 55.04,21.01 55.33,21.3 CN4.6
BOARD_ID9_SIM_TYPE2: length 1.7
  BOTTOM w0.114: R69070.2 55.09,22.03 55.32,21.8 CN4.5
BODY_SAR_ODL: length 4
  BOTTOM w0.114: D26.2 33.35,12.37 32.98,11.99 R13.1 32.79,11.3 CN3.25
CONFIG_0: length 2
  BOTTOM w0.114: TP2.1 33.96,10.51 33.79,10.35 CN3.21
CONFIG_1: length 2.6
  BOTTOM w0.114: CN3.69 21.79,10.52 21.33,10.98 TP3.1
CONFIG_2: length 2.5
  BOTTOM w0.114: TP4.1 19.27,10.01 19.53,10.27 20.04,10.27 20.29,10.01 CN3.75
CONFIG_3: length 1.9
  BOTTOM w0.114: TP5.1 38.53,10.39 38.79,10.12 CN3.1
CONN_LTE_WAKE_L: length 5.4
  BOTTOM w0.114: Q2.1 34.99,12.94 R12.2 34.49,11.49 34.39,11.59 33.88,11.59 33.29,11 CN3.23
CX: length 1.5
  BOTTOM w0.254: R33.2 U5.6
DDR4_SUSON_2V5: length 22.6
  IN1 w0.089: v1(57.2,11.64) 57.2,14.93 57.94,15.68 57.94,18.28 52.25,23.98 46.77,23.98 v1(46.56,24.19)
  BOTTOM w0.114: v1(57.2,11.64) 57.04,11.8 CN4.25 ; R350.1 v1(46.56,24.19)
EC_LTE_GPS_OFF_ODL: length 1.9
  TOP w0.114: TP1.1 v1(32.54,7.57)
  BOTTOM w0.114: CN3.26 v1(32.54,7.57)
EC_SIM_DET: length 56.5
  IN1 w0.089: v1(59.13,15.17) 58.62,15.68 58.62,18.34 52.52,24.43 48.64,24.43 47.8,25.27 21.36,25.27 17.68,21.59 v1(17.68,19.31)
  BOTTOM w0.114: v1(59.13,15.17) 57.53,15.17 57.16,14.8 CN4.19 ; Q4.3 17.62,17.59 v1(16.79,18.42) v1(17.68,19.31)
EC_SIM_DET_LTE: length 12
  IN4 w0.089: v1(20.83,11.74) 20.83,11.64 22.39,10.07 v1(22.39,7.57)
  BOTTOM w0.114: CN3.66 22.54,7.41 v1(22.39,7.57) ; v1(20.83,11.74) 20.78,11.79 R42.2 19.82,16.43 Q4.1
EC_SIM_SW#: length 43.4
  IN1 w0.089: v1(28.53,16.39) 32.53,16.39 33.92,17.77 33.92,20.44 38.37,24.89 45.18,24.89 46.28,23.79 51.94,23.79 57.75,17.97 57.75,16.05 v1(57,15.3)
  BOTTOM w0.114: U1.2 v1(28.53,16.39) ; CN4.18 v1(57,15.3)
EN_3V_DX_LTE: length 27
  TOP w0.114: R8.1 v1(35.73,10.59)
  IN4 w0.089: v1(35.73,10.59) 35.73,10.19 36.73,9.2 52.53,9.2 53.85,10.52 56.7,10.52 57.86,11.68 v1(57.86,11.87)
  BOTTOM w0.114: v1(57.86,11.87) 57.43,12.3 CN4.24
EN_3V_DX_LTE_R: length 4
  TOP w0.114: v1(35.73,8.06) R8.2
  BOTTOM w0.114: v1(35.73,8.06) 37.13,8.06 37.54,7.64 CN3.6
ENCLK: length 1.5
  BOTTOM w0.254: R39.1 43.09,23.55 42.96,23.42 U4.12
ESIM_CLK: length 32.8
  TOP w0.114: v1(4.14,8.06) C22.2 U6.6
  IN4 w0.089: v1(28.24,15.79) 25.52,18.51 20.08,18.51 17.43,15.86 17.43,15.36 13.73,11.66 8.4,11.66 4.8,8.06 v1(4.14,8.06)
  BOTTOM w0.114: v1(28.24,15.79) 28.1,15.93 R64.2
ESIM_CLK_S: length 1.2
  BOTTOM w0.114: U1.3 26.79,15.99 26.84,15.93 R64.1
ESIM_DATA: length 42.7
  TOP w0.114: v1(4.14,19.49) R347.1 C23.2 U6.3
  IN4 w0.089: v1(4.14,19.49) 2.44,17.79 2.44,8.57 4.28,6.72 10.26,6.72 13.89,10.36 13.89,11.03 14.79,11.93 18.31,11.93 20.13,13.75 24.05,13.75 v1(25.04,12.76)
  BOTTOM w0.114: v1(25.04,12.76) 25.08,12.76 25.19,12.87 R65.2
ESIM_DATA_S: length 1.3
  BOTTOM w0.114: U1.7 25.12,14.5 25.06,14.44 25.06,14.07 25.19,13.94 R65.1
ESIM_RST#: length 26.7
  TOP w0.114: v1(5.41,8.1) C21.2 U6.7
  IN4 w0.089: v1(5.41,8.1) 5.69,8.38 5.69,8.58 8.51,11.4 13.84,11.4 17.69,15.25 17.69,15.85 20.1,18.26 22.27,18.26 22.65,17.87 22.65,16.53 v1(22.3,16.19)
  BOTTOM w0.114: R66.2 v1(22.3,16.19)
ESIM_RST#_S: length 1.4
  BOTTOM w0.114: U1.11 23.85,16.39 23.65,16.19 R66.1
I2C_DX_LTE_1V8_RSUB_SCL: length 2.4
  BOTTOM w0.114: R4700.1 R316.1 U9314.B1
I2C_DX_LTE_1V8_RSUB_SDA: length 2.6
  BOTTOM w0.114: R4701.1 R299.1 22.93,22.79 23.3,22.43 U9314.A1
IO2: length 1.5
  BOTTOM w0.114: R38.1 29.8,15.3 U5.3
LTE_BODY_SAR_ODL: length 56.5
  TOP w0.114: v1(34.75,15.04) 34.75,13.92 33.92,13.1 29.95,13.1 29.35,13.69 29.35,14.91 29.53,15.08 29.53,18.06 28.28,19.31 25.91,19.31 25.45,18.85 22.49,18.85 v1(21.19,20.16)
  IN1 w0.089: v1(57.35,16.31) 56.29,17.37 56.29,18.45 53.03,21.71 48.41,21.71 47.08,20.38 44.12,20.38 39.63,15.89 35.22,15.89 34.75,15.42 v1(34.75,15.04)
  BOTTOM w0.114: v1(34.75,15.04) 34.67,14.97 D26.1 33.35,14.09 33.13,13.87 32.04,13.87 31.92,13.99 R37.2 R69075.2 ; CN4.17 56.84,15.8 v1(57.35,16.31) ; R4702.2 v1(21.19,20.16)
LTE_OFF_ODL: length 27.5
  TOP w0.114: R9.2 36.89,7.43 v1(36.75,7.56) ; R41.1 v1(59,12.25)
  IN1 w0.089: v1(36.75,7.56) 36.75,8.14 37.88,9.27 52.79,9.27 54.24,10.72 57.62,10.72 59,12.11 v1(59,12.25)
  BOTTOM w0.114: v1(36.75,7.56) 37.04,7.27 CN3.8
LTE_OFF_ODL_R: length 3
  TOP w0.114: v1(57.7,14.03) 57.94,13.78 R41.2
  BOTTOM w0.114: v1(57.7,14.03) 57.47,13.8 CN4.21
LTE_OFF_ODL_RST: length 1.9
  TOP w0.114: R1.2 55.57,12.38 v1(55.35,12.6)
  BOTTOM w0.114: v1(55.35,12.6) 55.55,12.8 CN4.23
LTE_SIM_CLK: length 10.3
  IN4 w0.089: v1(31.17,7.76) 31.17,9.16 27.89,12.45 v1(27.89,14.41)
  BOTTOM w0.114: R75.1 27.7,14.59 v1(27.89,14.41) ; v1(31.17,7.76) 31.04,7.63 CN3.32
LTE_SIM_DATA: length 12.4
  IN4 w0.089: v1(23.83,13.29) 23.83,12.64 24.94,11.54 28.53,11.54 30.54,9.52 v1(30.54,7.57)
  BOTTOM w0.114: v1(30.54,7.57) CN3.34 ; R76.1 v1(23.83,13.29)
LTE_SIM_RST#: length 18.8
  IN4 w0.089: v1(31.82,7.88) 31.82,8.78 28.29,12.32 28.29,14.74 27.94,15.09 24.1,15.09 23.54,15.65 22.07,15.65 21.66,16.06 21.66,16.37 v1(22.25,16.95)
  BOTTOM w0.114: CN3.30 31.54,7.35 31.82,7.63 v1(31.82,7.88) ; R77.1 v1(22.25,16.95)
NB680_VCC_BYP: length 1.6
  BOTTOM w0.254: C27.1 41.33,23.55 41.46,23.42 U4.9
P_SENS_CS1: length 7.6
  IN1 w0.089: v1(21.39,23.54) 20.52,22.68 20.52,21.4 21.34,20.59 v1(23.7,20.59)
  BOTTOM w0.114: J11.1 20.98,23.96 v1(21.39,23.54) ; U9314.B3 v1(23.7,20.59)
P_SENSOR_INT_RSUB_L: length 2.4
  BOTTOM w0.114: U9314.A2 R558_46.1 R4702.1
PCIE_WAKE#: length 31.5
  TOP w0.114: v1(55.35,13.39) R3.1
  IN1 w0.089: v1(35.51,15.04) 36.02,15.55 39.55,15.55 41.39,17.39 41.39,17.39 44.2,20.19 47.16,20.19 48.48,21.52 52.95,21.52 56.1,18.37 56.1,14.14 v1(55.35,13.39)
  BOTTOM w0.114: Q2.3 v1(35.51,15.04)
PCIE_WAKE#_R: length 2.3
  TOP w0.114: v1(57.73,13.3) 57.7,13.3 57.61,13.39 R3.2
  BOTTOM w0.114: CN4.22 v1(57.73,13.3)
PLT_RST_LTE_L: length 4.6
  BOTTOM w0.114: CN3.67 22.29,10.42 21.9,10.82 Q3.1 22.63,12.19 R32.2
PLTRST#: length 56.1
  TOP w0.114: v1(57.99,12.6) 57.76,12.38 R1.1
  IN1 w0.089: v1(19.86,14.08) 19.86,14.33 21.08,15.55 23.43,15.55 27.27,19.39 27.27,23.65 28.7,25.08 47.67,25.08 48.54,24.21 52.43,24.21 58.13,18.5 58.13,12.75 v1(57.99,12.6)
  BOTTOM w0.114: v1(19.86,14.08) 19.9,14.04 Q3.3
PP3300_A: length 14.1
  IN1 w0.508: v1(20.93,22.22) 22.93,22.22 23.7,22.99 v1(23.7,24.55)
  IN4 w0.508: v1(26.75,19.97) 24.51,22.22 v1(20.93,22.22)
  BOTTOM w0.203: v1(20.93,22.22) 21.19,21.97 R558_46.2 ; R299.2 R316.2 v1(23.7,24.55)
  BOTTOM w0.508: R4704.2 v1(26.75,19.97)
SIM_CLK: length 16.9
  TOP w0.114: v1(12.39,9.84) R6.1
  IN1 w0.089: v1(12.39,9.84) 14.35,11.79 19.68,11.79 20.45,12.55 24.08,12.55 24.74,13.21 25.6,13.21 v1(26.06,12.76)
  BOTTOM w0.114: R60.2 26.08,12.78 v1(26.06,12.76)
SIM_CLK_S: length 1.3
  BOTTOM w0.114: U1.5 25.92,14.51 26.08,14.34 R60.1
SIM_DATA: length 18.2
  TOP w0.114: v1(8.33,9.84) R7.1
  IN1 w0.089: v1(22.3,14.92) 19.38,11.99 9.85,11.99 8.33,10.47 v1(8.33,9.84)
  BOTTOM w0.114: R59.2 22.43,14.92 v1(22.3,14.92)
SIM_DATA_S: length 1.4
  BOTTOM w0.114: U1.9 23.95,15.59 23.66,15.3 R59.1
SIM_RST#: length 15.4
  TOP w0.114: v1(10.36,16.31) R5.1
  IN1 w0.089: v1(22.25,17.71) 19.33,14.79 11.89,14.79 v1(10.36,16.31)
  BOTTOM w0.114: R61.2 v1(22.25,17.71)
SIM_RST#_S: length 1.6
  BOTTOM w0.114: U1.13 23.97,17.36 23.62,17.71 R61.1
SX9310_GND: length 15
  TOP w0.508: v1(18.74,23.49) 18.31,23.92 v1(18.31,24.45) 18.31,24.98 v1(18.74,25.41)
  IN1 w0.508: v1(26.72,22.28) v1(26.72,21.52) 23.23,21.52 v1(22.76,21.06)
  IN4 w0.508: v1(18.74,23.49) 18.74,22.41 20.1,21.06 v1(22.76,21.06)
  BOTTOM w0.114: U9314.B2 U9314.A3
  BOTTOM w0.203: C45637.2 v1(26.72,21.52) ; C45636.2 v1(26.72,22.28)
  BOTTOM w0.254: v1(22.76,21.06) 22.83,21.12 U9314.A3
USB2_3_A1_S_N: length 26
  BOTTOM w0.114: R11.2 36.86,11.77 36.86,15.67 38.77,17.58 45.06,17.58 47.33,19.86 47.81,19.86 48.29,20.34 52.32,20.34 53.85,18.8 CN4.11
USB2_3_A1_S_N_R: length 2.2
  BOTTOM w0.114: R11.1 36.93,10.88 36.93,10.14 36.79,10 CN3.9
USB2_3_A1_S_P: length 26
  BOTTOM w0.114: R10.2 37.21,11.58 37.09,11.7 37.09,15.58 38.87,17.35 45.15,17.35 47.43,19.63 47.9,19.63 48.39,20.11 52.22,20.11 53.76,18.57 55.41,18.57 55.68,18.3 CN4.12
USB2_3_A1_S_P_R: length 2.3
  BOTTOM w0.114: CN3.7 37.29,10 37.16,10.14 37.16,10.86 R10.1
USIM2_CLK: length 2.1
  TOP w0.114: v1(28.12,7.57) 28.12,6.78 TP12.1
  BOTTOM w0.114: CN3.44 28.04,7.49 v1(28.12,7.57)
USIM2_DATA: length 2.5
  TOP w0.114: v1(28.69,7.89) 28.88,8.08 TP13.1
  BOTTOM w0.114: v1(28.69,7.89) 28.69,7.53 28.54,7.38 CN3.42
USIM2_DET: length 2.2
  TOP w0.114: TP10.1 29.27,6.9 v1(29.27,7.56)
  BOTTOM w0.114: CN3.40 29.04,7.34 v1(29.27,7.56)
USIM2_RESET: length 2.4
  TOP w0.114: v1(27.54,7.9) TP14.1
  BOTTOM w0.114: CN3.46 v1(27.54,7.9)
USIM2_VDD: length 2.2
  TOP w0.114: v1(26.92,7.57) 26.92,6.71 TP11.1
  BOTTOM w0.114: v1(26.92,7.57) 26.93,7.57 27.04,7.46 CN3.48
USIM_CLK: length 1.3
  BOTTOM w0.114: U1.4 26.72,15.59 27.13,15.17 R75.2
USIM_CLK_R: length 6.6
  TOP w0.114: L4.1 13.46,11.23 12.24,12.45 11.68,12.45 11.48,12.65 11.47,12.65 11.38,12.75 D2.2 10.98,12.29 11.38,11.89 C4.2 R6.2
USIM_CLK_R_L: length 2.8
  TOP w0.114: L4.2 15.7,11.23 15.81,11.35 D13142.2 16.5,11.35 16.54,11.3 v1(16.87,11.3)
  BOTTOM w0.114: CN5.7 v1(16.87,11.3)
USIM_DATA: length 1.4
  BOTTOM w0.114: U1.8 24.72,14.23 24.43,13.94 R76.2
USIM_DATA_R: length 8.7
  TOP w0.114: v1(9.96,12.5) 10.06,12.5 10.3,12.75 D2.1 10.51,12.74 10.51,12.15 10.36,11.99 C3.2 R4.2 R7.2 ; L3.1 13.97,12.25 v1(13.71,12.5)
  BOTTOM w0.114: v1(13.71,12.5) v1(9.96,12.5)
USIM_DATA_R_L: length 2.9
  TOP w0.114: v1(16.87,12.43) 16.8,12.49 D13143.2 15.78,12.49 15.54,12.25 L3.2
  BOTTOM w0.114: CN5.6 16.64,12.2 v1(16.87,12.43)
USIM_DET#: length 74.1
  TOP w0.114: v1(10.82,14.23) 10.5,13.91 D2.4 10.2,13.53 v1(9.9,13.82)
  IN1 w0.089: v1(9.9,13.82) 9.5,14.23 9.5,16.62 11.12,18.24 14.06,18.24 21.32,25.51 48.06,25.51 48.67,24.9 52.48,24.9 59.13,18.24 59.13,16.41 59.59,15.96 59.59,14.74 59.49,14.64 58.65,14.64 v1(58.62,14.61)
  BOTTOM w0.114: CN4.20 57.24,14.3 57.55,14.61 v1(58.62,14.61) ; CN5.2 15.03,15.8 14.12,14.89 10.97,14.89 10.82,14.74 v1(10.82,14.23)
USIM_RST#: length 1.4
  BOTTOM w0.114: U1.12 23.8,16.79 23.63,16.95 R77.2
USIM_RST_L: length 6.3
  TOP w0.114: R5.2 C5.2 11.38,14.13 10.98,13.73 D2.3 11.53,13.53 12.15,12.91 13.46,12.91 13.82,13.26 L2.1
USIM_RST_L_L: length 2.8
  TOP w0.114: v1(16.87,13.1) 16.82,13.15 D13144.2 15.81,13.15 15.7,13.26 L2.2
  BOTTOM w0.114: CN5.5 v1(16.87,13.1)
N157273: length 5.5
  BOTTOM w0.114: U4.11 C32.1 43.5,24.43 44.27,25.2 R349.1 R350.2
N157401: length 1.7
  BOTTOM w0.254: U4.6 41.46,19.37 40.95,18.86 C33.1
N157503: length 1.2
  BOTTOM w0.254: U4.3 R40.1
N170649: length 2.4
  TOP w0.508: v1(30.68,17.79) 30.3,17.4 R36.2
  BOTTOM w0.508: U5.5 30.75,17.85 v1(30.68,17.79)
N170657: length 3.4
  TOP w0.254: SPR1.1 v1(30.87,22.6)
  BOTTOM w0.254: R33.1 D3.1 v1(30.87,22.6)
N194065:
  vias: v2(54.4,9.84) v2(54.4,9.07) v2(55.28,9.84) v2(55.28,9.07)
N213722: length 2
  TOP w0.406: v1(55.35,16.8) 55.57,17.02 R69074.1
  BOTTOM w0.305: CN4.15 v1(55.35,16.8)
N15816409: length 2.8
  BOTTOM w0.201: R345.2 23.8,18.59 R346.2 25.12,18.31 U1.14
N15891397: length 1
  BOTTOM w0.114: R349.2 R348.1
N15913509: length 2.3
  BOTTOM w0.508: CN5.4 16.85,14 F1.2
N15931362: length 1.4
  BOTTOM w0.114: R69075.1 31.47,15.33 31.7,15.55 U5.1
N15932503: length 2.6
  BOTTOM w0.114: U9314.C2 C45637.1 25.76,20.85 R4704.1
N15934474: length 8.8
  IN4 w0.089: v1(24.54,7.57) 26,7.57 27.2,8.77 v1(27.2,10.64)
  BOTTOM w0.114: CN3.58 v1(24.54,7.57) ; v1(27.2,10.64) D13145.2 27.88,12.17 R69079.2
N15935166: length 2.9
  TOP w0.114: R69080.1 v1(58.39,19.74)
  BOTTOM w0.114: v1(58.39,19.74) 58.22,19.92 56.92,19.92 56.8,19.8 CN4.9
N15935178: length 2.9
  TOP w0.114: R69081.1 v1(58.39,20.5)
  BOTTOM w0.114: CN4.8 56.8,20.3 56.92,20.18 58.07,20.18 v1(58.39,20.5)

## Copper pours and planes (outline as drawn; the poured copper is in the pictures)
3V_A_R on BOTTOM (solid shape): 38.13,22.29 38.13,20 38.02,19.88 34.28,19.88 34.14,20.02 34.14,21.14 33.53,21.75 33.53,22.48 33.63,22.59 37.84,22.59
3V_SW on BOTTOM (solid shape): 39.65,23.37 39.65,22.78 39.9,22.52 39.9,22.46 40.74,21.61 40.81,21.61 40.9,21.52 41.62,21.52 42.44,21.52 42.49,21.47 42.49,21.23 42.44,21.17 42.01,21.17 41.98,21.17 41.93,21.15 41.53,21.15 40.18,19.8 38.9,19.8 38.71,20 38.71,23.51 38.83,23.64 39.38,23.64
+1.8V_DX_LTE on BOTTOM (solid shape): 39.67,13.15 39.67,12.45 39.1,11.88 38.4,11.88 38.13,12.15 38.13,13.09 38.29,13.24 39.58,13.24
+3V on BOTTOM (solid shape): 56.94,24.88 56.94,23.34 56.77,23.17 54.56,23.17 54.28,23.45 56.59,23.45 56.59,23.65 55.76,23.65 55.76,23.45 54.28,23.45 54.14,23.59 54.14,24.91 54.32,25.09 56.73,25.09
+3V on BOTTOM (solid shape): 20.78,20.16 20.9,19.87 21.19,19.75 21.55,19.39 22.52,19.39 22.69,19.21 22.69,18.48 22.57,18.36 21.13,18.36 20.2,19.28 19.38,19.28 19.07,19.59 19.07,20.36 19.23,20.52 20.42,20.52
+3V on IN2 (solid shape): outline of 547 points within 20.59,17.29 56.59,25.68
+3V_DX_LTE on TOP (solid shape): 20.12,10.88 20.12,10.11 20.42,9.81 21.33,9.81 21.59,9.56 21.59,7.51 21.43,7.36 19.95,7.36 19.77,7.54 19.77,7.56 19.66,8.01 19.39,8.39 18.86,8.68 18.26,8.69 18.13,8.69 17.88,8.95 17.88,9.86 17.47,10.27 17.47,11.03 17.58,11.13 19.86,11.13
+3V_DX_LTE on TOP (solid shape): outline of 139 points within 37,6.79 41.45,12.12
+3V_DX_LTE on BOTTOM (solid shape): 19.3,11.79 19.3,10.62 18.95,10.27 17.58,10.27 17.42,10.42 17.42,11.89 17.58,12.04 19.05,12.04
+3V_DX_LTE on BOTTOM (solid shape): 53.27,9.53 53.27,6.56 52.93,6.22 51.81,6.22 51.61,6.42 51.61,9.64 51.75,9.78 53.02,9.78
+3V_DX_LTE on BOTTOM (solid shape): 42.81,13.19 42.9,13.13 43.23,12.81 43.23,9.71 42.97,9.45 39.98,9.45 39.85,9.58 39.85,13.12 39.91,13.19
+3V_DX_LTE on BOTTOM (solid shape): 37.64,18.95 37.64,17.09 36.86,16.31 34.42,16.31 34.26,16.46 34.26,18.8 34.39,18.93 35.94,18.93 36.05,18.98 36.09,19.08 36.09,19.13 37.46,19.13
+3V_DX_LTE on BOTTOM (solid shape): 23.37,20.34 23.52,20.22 23.7,20.18 23.88,20.22 24.02,20.34 24.9,20.34 25.13,20.11 25.13,19.27 24.97,19.11 24.59,19.11 24.26,19.44 22.78,19.44 22.58,19.64 22.58,20.16 22.76,20.34
+3V_DX_LTE on BOTTOM (solid shape): 21.87,7.73 21.87,7.31 21.84,7.3 21.79,7.26 21.76,7.2 21.75,7.16 21.68,7.16 21.68,5.67 21.41,5.67 21.41,7.16 21.18,7.16 21.18,5.67 20.91,5.67 20.91,7.16 20.68,7.16 20.68,5.67 20.26,5.67 20.07,5.91 19.81,6.08 19.81,7.85 20,8.04 21.55,8.04
+3V_DX_LTE on BOTTOM (solid shape): 39.64,8.18 39.73,8.13 39.73,8.03 39.57,7.44 39.8,6.88 39.8,6.27 39.77,6.2 39.7,6.17 39.19,6.04 38.82,5.67 38.41,5.67 38.41,7.16 38.18,7.16 38.18,5.67 37.91,5.67 37.91,7.16 37.89,7.16 37.89,8.1 37.91,8.13 37.94,8.15 37.98,8.16 38.02,8.17 38.04,8.18 38.07,8.17 38.11,8.15 38.16,8.15 38.43,8.15 38.48,8.15 38.52,8.17 38.54,8.18 38.57,8.17 38.61,8.15 38.65,8.15 38.93,8.15 38.98,8.15 39.02,8.17 39.03,8.18
+3V_DX_LTE on IN2 (solid shape): outline of 3510 points within 16.61,1.53 53.59,20.27
+5VPCU on TOP (solid shape): 59.8,10.86 59.8,8.45 59.56,8.21 57.44,8.21 57.17,8.48 57.17,10.89 57.43,11.14 59.52,11.14
+5VPCU on BOTTOM (solid shape): 49.83,23.3 49.83,22.93 49.82,22.92 49.82,21.91 49.63,21.72 42.06,21.72 41.98,21.8 41.98,22.08 42.15,22.24 43.27,22.24 44.22,23.19 44.34,23.19 44.46,23.24 44.51,23.36 44.51,23.49 44.7,23.68 49.45,23.68
+5VPCU on IN2 (solid shape): outline of 1028 points within 48.41,8.97 61.01,23.93
GND on TOP (solid shape): outline of 3670 points within 0.53,0.53 62.07,31.47
GND on BOTTOM (solid shape): 31.04,17.02 31.04,15.11 30.94,15 30.36,15 30.22,15.14 30.22,15.5 30.38,15.65 30.38,16.97 30.48,17.07 30.99,17.07
GND on BOTTOM (solid shape): 45.51,12.76 45.96,12.02 46.53,11.38 46.53,9.33 46.15,8.95 43.99,8.95 43.48,9.45 43.48,12.38 43.86,12.76
GND on BOTTOM (solid shape): outline of 1512 points within 0.53,0.53 62.07,31.47
GND on SGND (solid shape): outline of 518 points within 0.51,0.51 62.09,31.49
GND on IN1 (solid shape): outline of 1992 points within 20.43,7.11 58,24.94
GND on IN1 (solid shape): outline of 2307 points within 0.53,0.53 62.07,31.47
GND on SVCC (solid shape): outline of 518 points within 0.51,0.51 62.09,31.49
GND on IN2 (solid shape): 44.33,24.25 44.37,24.16 44.37,24.15 44.47,23.89 44.72,23.78 46.08,23.78 46.19,23.8 46.3,23.86 46.42,23.79 46.56,23.77 46.69,23.79 46.82,23.86 46.92,23.8 47.04,23.78 48.16,23.78 48.26,23.72 48.23,23.61 48.16,23.53 48.16,22.2 50.63,19.72 50.72,19.71 53.61,18.1 54.76,15 54.37,13.11 53.26,11.53 53.26,11.33 52.48,10.55 51.72,10.55 51.53,10.49 50.77,10.3 50,10.24 47.11,11.21 45.41,13.74 45.37,13.84 45.3,13.91 45.28,13.95 45.29,13.99 45.58,14.46 45.68,15 45.45,15.8 44.84,16.37 44.81,16.4 44.82,16.44 44.85,16.52 44.86,16.6 44.86,18.91 43.63,20.14 38.54,20.14 38.47,20.17 38.44,20.24 38.44,20.25 38.32,20.55 38.02,20.67 37.85,20.63 37.71,20.53 35.2,20.53 34.93,20.81 34.93,21.57 37.14,23.78 41.69,23.78 41.77,23.88 41.87,23.93 41.97,23.88 42.05,23.78 43.76,23.78 44.02,23.89 44.11,24.15 44.11,24.16 44.15,24.25 44.24,24.28
GND on IN2 (solid shape): outline of 1325 points within 0.53,0.53 62.07,31.47
GND on IN3 (solid shape): outline of 6233 points within 0.53,0.53 62.07,31.47
GND on SGND1 (solid shape): outline of 518 points within 0.51,0.51 62.09,31.49
GND on IN4 (solid shape): outline of 428 points within 14.87,11.68 28.3,18.11
GND on IN4 (solid shape): outline of 4821 points within 0.53,0.53 62.07,31.47
GND on SGND2 (solid shape): outline of 518 points within 0.51,0.51 62.09,31.49
+ESIM_PWR_S on BOTTOM (solid shape): 25.51,18.86 25.89,18.86 25.98,18.8 25.98,18.38 25.62,18.02 25.62,17.04 25.42,17.04 25.42,17.69 25.37,17.73 25.37,18.79 25.45,18.86
+LTE_SIM_PWR on TOP (solid shape): 30.72,9.67 30.72,8.01 30.67,7.96 30.59,7.97 30.54,7.97 30.27,7.86 30.14,7.6 30.14,7.55 29.68,7.55 29.68,7.6 29.63,7.76 29.51,7.89 29.51,9.68 29.65,9.82 30.57,9.82
+SIM_PWR on BOTTOM (solid shape): 28.51,18.04 28.51,17.28 28.48,17.2 28.48,17.12 28.48,17.05 28.51,16.96 28.51,16.79 28.47,16.79 28.33,16.74 28.23,16.66 27.77,16.66 27.72,16.71 27.72,16.87 27.72,16.88 27.72,17.26 27.72,17.28 27.72,17.99 27.91,18.18 28.37,18.18
+SIM_PWR_S on BOTTOM (solid shape): 27.49,17.27 27.49,16.88 27.49,16.85 27.51,16.82 27.51,16.66 27.47,16.62 26.54,16.62 26.47,16.68 25.66,16.68 25.66,16.89 26.07,16.89 26.48,17.29 27.47,17.29
+USIM_PWR on BOTTOM (solid shape): 26.58,19 26.58,18.99 26.57,18.97 26.57,18.94 26.57,18.56 26.57,18.54 26.58,18.52 26.58,17.61 26.01,17.04 25.84,17.04 25.84,18.03 26.14,18.32 26.14,18.99 26.2,19.06 26.53,19.06
PP3300_A on BOTTOM (solid shape): 21.35,22.42 21.35,21.38 21.26,21.29 20.48,21.29 20.22,21.02 19.23,21.02 19.18,21.07 19.18,22.08 19.63,22.54 21.23,22.54
SX9310_GND on BOTTOM (solid shape): 19.81,23.7 20.76,23.7 20.76,23.24 19.21,23.24 18.51,22.54 17.85,22.54 17.74,22.65 17.74,23.55 17.93,23.74 19.77,23.74
N170613 on BOTTOM (solid shape): 29.41,20.38 29.92,20.38 30.12,20.17 30.12,18.39 29.95,18.22 28.98,18.22 28.4,18.8 28.4,20.73 28.45,20.78 29.01,20.78
N194065 on TOP (solid shape): 56.76,10.72 56.76,8.53 56.58,8.35 54.57,8.35 54.05,8.87 54.05,10.34 54.72,11.02 56.46,11.02
N194065 on BOTTOM (solid shape): 54.57,10.97 54.62,10.96 54.65,10.96 55.19,10.96 55.21,10.98 55.76,10.98 55.76,10.95 56.59,10.95 56.59,10.98 56.81,10.98 56.94,10.85 56.94,9.2 56.55,8.82 54.27,8.82 54.01,9.07 54.01,9.45 56.59,9.45 56.59,9.65 55.76,9.65 55.76,9.45 54.01,9.45 54.01,9.95 56.59,9.95 56.59,10.15 55.76,10.15 55.76,9.95 54.01,9.95 54.01,10.45 56.59,10.45 56.59,10.65 55.76,10.65 55.76,10.45 54.01,10.45 54.01,10.85 54.14,10.98 54.46,10.98
N15932419 on BOTTOM (solid shape): 26.48,25.33 26.48,23.03 26.38,22.93 26.19,22.93 25.91,22.66 25.91,22.1 25.67,21.86 25.66,21.86 25.56,21.82 25.5,21.73 24.25,21.73 24.21,21.77 24.03,21.77 23.96,21.83 23.96,22.04 24.1,22.17 25.29,22.17 25.5,22.39 25.5,23.14 25.52,23.15 25.52,25.23 25.68,25.39 26.41,25.39

Small or netless copper shapes (teardrops, artwork), in the pictures only: 4 on BOTTOM, 1 on IN4

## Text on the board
Ref Des/Silkscreen Bottom: REV:C | DAZ8IAPCAC0
User.Comments: 26.7 | 62.6 | 29 | 32
Ref Des/Silkscreen Top: MODEL:Z8IA-LTE | DAZ8IAPCAC0 | REV:C
User.45: FIGURE | SIZE | 10.0 | 14.0 | 118.0 | 47.0 | 67.0 | 91.0 | 51.0x22.0 | 197.0x157.0 | 102.0x91.0 | DRILL CHART: TOP to BOTTOM | ALL UNITS ARE IN MILS | SLOT HOLES: TOP to BOTTOM | PLATED | NON-PLATED | QTY | 212 | 45 | 2 | 1 | 262 | 4 | 6 | TOTAL HOLES:
